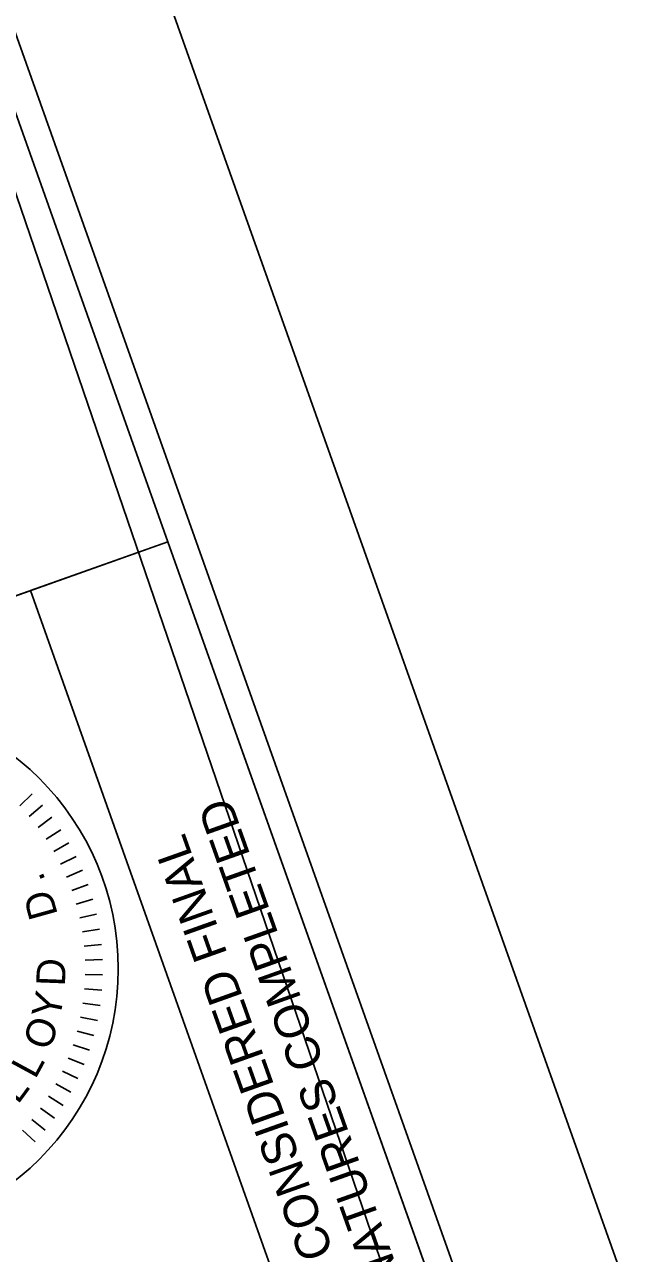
# Model space of a CAD drawing. Extents: x 1615843 to 1618439, y 899470 to 903922.
# Drawn here: x 1616956.1 to 1617054.4, y 903439.2 to 903637 of the extents above; entities that cross this region are included whole.
import ezdxf

# ---------------------------------------------------------------- set-up
doc = ezdxf.new("R2010")
doc.units = 0
for name, color, linetype in [('Default', 7, 'Continuous'), ('DEV BORDER CELL', 7, 'Continuous'), ('Sheet Clip Boundary CELL', 7, 'Continuous'), ('Sheet Plot Border Outside CELL', 7, 'Continuous'), ('Sheet Sticker Exception Certification CELL', 7, 'Continuous')]:
    doc.layers.add(name, color=color, linetype=linetype)

msp = doc.modelspace()

# ---------------------------------------------------------------- linework, layer by layer
at = {"layer": 'Default'}
for p, q in [((1616957.3, 903513.18), (1616955.29, 903511.26)), ((1616958.95, 903511.35), (1616956.83, 903509.55)), ((1616960.49, 903509.42), (1616958.26, 903507.75)), ((1616961.91, 903507.4), (1616959.58, 903505.87)), ((1616963.21, 903505.3), (1616960.79, 903503.91)), ((1616964.37, 903503.12), (1616961.88, 903501.88)), ((1616965.4, 903500.88), (1616962.84, 903499.79)), ((1616966.3, 903498.58), (1616963.67, 903497.65)), ((1616967.05, 903496.23), (1616964.38, 903495.45)), ((1616967.66, 903493.83), (1616964.95, 903493.23)), ((1616968.13, 903491.41), (1616965.38, 903490.97)), ((1616968.45, 903488.96), (1616965.68, 903488.68)), ((1616968.62, 903486.5), (1616965.83, 903486.39)), ((1616968.64, 903484.03), (1616965.85, 903484.09)), ((1616968.51, 903481.56), (1616965.73, 903481.79)), ((1616968.23, 903479.11), (1616965.47, 903479.51)), ((1616967.81, 903476.68), (1616965.08, 903477.24)), ((1616967.24, 903474.27), (1616964.55, 903475)), ((1616966.52, 903471.91), (1616963.88, 903472.8)), ((1616965.66, 903469.59), (1616963.08, 903470.64)), ((1616964.67, 903467.34), (1616962.16, 903468.53)), ((1616963.54, 903465.14), (1616961.1, 903466.49)), ((1616960.9, 903460.97), (1616958.64, 903462.6)), ((1616962.28, 903463.01), (1616959.93, 903464.51)), ((1616959.39, 903459.02), (1616957.23, 903460.78)), ((1616957.77, 903457.15), (1616955.72, 903459.05))]:
    msp.add_line(p, q, dxfattribs=at)
at = {"layer": 'DEV BORDER CELL'}
msp.add_line((1616871.74, 903515.59), (1616979.16, 903553.77), dxfattribs=at)
for points in [[(1615874.87, 903538.12), (1616377.33, 902124.77), (1617366.67, 902476.49), (1616864.22, 903889.84)], [(1616849.6, 903507.72), (1616811.41, 903615.13), (1616940.97, 903661.19), (1616979.16, 903553.77)], [(1616916.61, 903319.23), (1616849.6, 903507.72), (1616979.16, 903553.77), (1617046.17, 903365.29)]]:
    msp.add_lwpolyline(points, close=True, dxfattribs=at)
msp.add_circle((1616927.82, 903485.01), 43.34, dxfattribs=at)
at = {"layer": 'Sheet Clip Boundary CELL'}
msp.add_lwpolyline([(1616920.55, 902382.99), (1616489.91, 902364.33), (1616361.78, 902925.96), (1616113.49, 903406.12), (1616903.33, 903759.78), (1617118.27, 903131.4), (1617236.29, 902693.96), (1617083.45, 902390.05)], close=True, dxfattribs=at)
at = {"layer": 'Sheet Plot Border Outside CELL'}
for points in [[(1617444.82, 902331.28), (1616879.4, 903921.77), (1615842.94, 903553.3), (1616408.37, 901962.82)], [(1617444.82, 902331.28), (1616408.37, 901962.82), (1615842.94, 903553.3), (1616879.4, 903921.77)]]:
    msp.add_lwpolyline(points, close=True, dxfattribs=at)
at = {"layer": 'Sheet Sticker Exception Certification CELL'}
for p, q in [((1616957.03, 903545.91), (1616979.17, 903553.78)), ((1616979.16, 903553.77), (1617046.17, 903365.29)), ((1617024.02, 903357.42), (1616957.02, 903545.9))]:
    msp.add_line(p, q, dxfattribs=at)

# ---------------------------------------------------------------- texts
at = {"layer": 'Default'}
for s, rotation, p in [('.', 113.35, (1616959.54, 903499.27)), ('D', 105.6076, (1616961.46, 903493.74)), ('D', 87.8123, (1616962.57, 903482.16)), ('Y', 78.8398, (1616961.7, 903476.73)), ('O', 70.1672, (1616960.07, 903471.68)), ('L', 61.5245, (1616957.8, 903467.13)), ('L', 53.4527, (1616955.01, 903463.09))]:
    msp.add_text(s, height=4.64, rotation=rotation, dxfattribs=at).set_placement(p)
at = {"layer": 'Sheet Sticker Exception Certification CELL'}
for s, p in [('UNLESS ALL SIGNATURES COMPLETED', (1617036.7, 903378.91)), ('DOCUMENT NOT CONSIDERED FINAL', (1617026.71, 903380.74))]:
    msp.add_text(s, height=5.5, rotation=109.5707, dxfattribs=at).set_placement(p)

doc.saveas('drawing.dxf')
